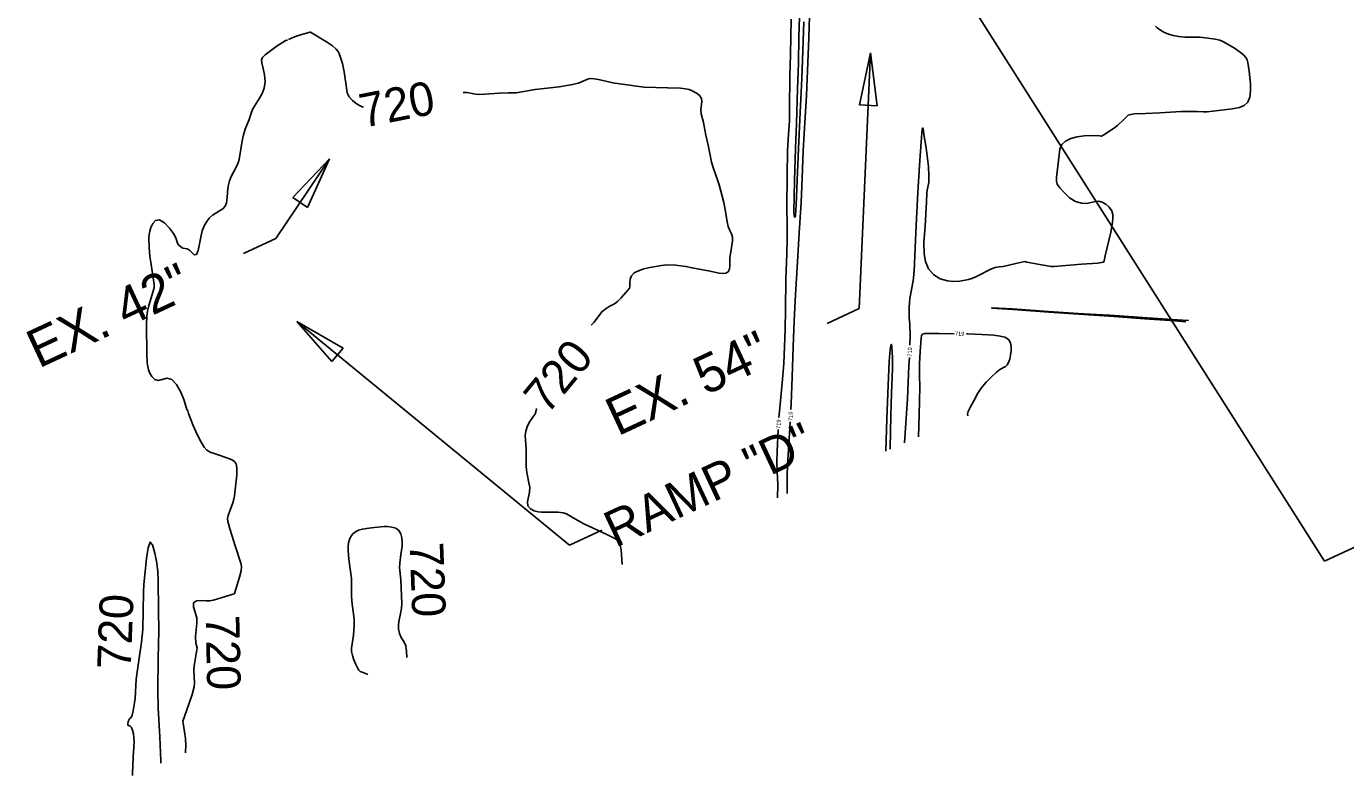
# Model space of a CAD drawing. Extents: x -310467766 to 17062430, y -322263100 to 8322522.
# Drawn here: x 1396172 to 1397464, y 572172 to 572906 of the extents above; entities that cross this region are included whole.
import ezdxf

# ---------------------------------------------------------------- set-up
doc = ezdxf.new("R2010")
doc.units = 0
for name, color, linetype in [('DT_X_Contour_Minor', 7, 'Continuous'), ('Level 19', 7, 'Continuous'), ('Level 40', 7, 'Continuous')]:
    doc.layers.add(name, color=color, linetype=linetype)

msp = doc.modelspace()

# ---------------------------------------------------------------- linework, layer by layer
at = {"layer": 'DT_X_Contour_Minor'}
for points in [[(1396939.3, 572926.2), (1396938.5, 572894.7), (1396937.1, 572862.4), (1396936, 572838), (1396934.1, 572806.2), (1396932.9, 572783.7), (1396931.9, 572757.4), (1396930.7, 572733.3), (1396928.9, 572703.5), (1396927.2, 572675.2), (1396925.2, 572642.8), (1396924, 572617.6), (1396923.1, 572591.8), (1396922.1, 572562), (1396921, 572536), (1396920.7, 572530.3)], [(1396929.6, 572924.9), (1396928.7, 572895.1), (1396928.1, 572869.8), (1396927.4, 572844.7), (1396926.2, 572810.5), (1396925.4, 572786.2), (1396924.4, 572754.4), (1396923.8, 572724.4), (1396924, 572720.5), (1396924.4, 572719), (1396924.7, 572718.8), (1396925, 572719), (1396925.3, 572720.4), (1396926, 572730.9), (1396927.4, 572763.1), (1396928.6, 572793.3), (1396929.8, 572821.4), (1396931.4, 572854.9), (1396932.5, 572881.7), (1396933.5, 572910.4)], [(1396909.1, 572522.6), (1396909.8, 572531.7), (1396912.8, 572563.6), (1396913.7, 572575.5), (1396915.1, 572608.8), (1396915.5, 572628.2), (1396915.9, 572658.2), (1396916.8, 572682.9), (1396917.2, 572697.2), (1396917, 572710.3), (1396916.8, 572729.3), (1396917.2, 572758.9), (1396917.3, 572784.6), (1396918.4, 572800), (1396919.3, 572813.3), (1396919.5, 572825.4), (1396919.7, 572857), (1396920.3, 572878.2), (1396920.9, 572912.9)], [(1396501.9, 572826.8), (1396500, 572827.2), (1396497.9, 572828.3), (1396494.7, 572830.4), (1396491.1, 572833.2), (1396488, 572836.7), (1396486.1, 572840.8), (1396485.2, 572845.5), (1396483.1, 572861.3), (1396481.3, 572869.6), (1396478.1, 572879.2), (1396477.1, 572881.1), (1396475.1, 572883.6), (1396471.5, 572886.8), (1396465.8, 572890.6), (1396450, 572900.1), (1396449.6, 572900.1), (1396440.1, 572897.5), (1396434.2, 572895.5)], [(1397368.5, 572831.5), (1397370.6, 572836.6), (1397371.2, 572842.8), (1397371, 572849.6), (1397369.8, 572861.9), (1397368.6, 572870.3), (1397367.9, 572872.9), (1397366.6, 572875.3), (1397364.3, 572877.8), (1397361.5, 572880.2), (1397355.5, 572884.4), (1397344.6, 572890.8), (1397341, 572892.2), (1397336.4, 572893.3), (1397327.1, 572894.6), (1397321.1, 572895.1), (1397306.9, 572895.3), (1397300.9, 572895.8), (1397295.5, 572896.9), (1397290.7, 572898.3), (1397286.8, 572899.9), (1397283.9, 572901.5), (1397279.7, 572904.5), (1397278, 572906.1)], [(1396427.5, 572892.6), (1396425.2, 572891.5), (1396417.5, 572886.9), (1396410.7, 572882), (1396405.7, 572877.9), (1396402.9, 572875.3), (1396402, 572873.1), (1396402.5, 572870), (1396403.8, 572864.7), (1396405.1, 572858.2), (1396405.5, 572851.4), (1396404.6, 572845.4), (1396402.6, 572840.1), (1396400.1, 572835.6), (1396393.5, 572825.1), (1396392.2, 572821.9), (1396389.9, 572814.7), (1396386.1, 572805.1), (1396384.4, 572799.6), (1396383.1, 572793.8), (1396380.1, 572775.4), (1396379.3, 572772.1), (1396377.6, 572768.5), (1396374.6, 572763.1), (1396372.6, 572759.2), (1396370.7, 572754.5), (1396369.4, 572749.2), (1396368.8, 572743.4), (1396368.5, 572737.8), (1396367.8, 572733), (1396366.3, 572729.5), (1396364, 572727), (1396361, 572725), (1396354.1, 572720.7), (1396350.9, 572718), (1396348.3, 572714.6), (1396346.2, 572711.1), (1396343.8, 572705.3), (1396343.1, 572702.5), (1396340, 572686.1), (1396338.3, 572682.1), (1396336.2, 572681.8), (1396331.5, 572686.5), (1396329.3, 572687.8), (1396325, 572688.6), (1396322.9, 572689.7), (1396321, 572691.5), (1396319.7, 572693.5), (1396318, 572698.6), (1396315.9, 572702.7), (1396311.9, 572708.1), (1396306.9, 572713.3), (1396302, 572716.3), (1396298.2, 572715.7), (1396295.5, 572712.6), (1396293.7, 572708.6), (1396292.6, 572705.2), (1396291.9, 572702), (1396291.7, 572698.3), (1396292, 572688.9), (1396292.6, 572680.6), (1396293.9, 572672.6), (1396297, 572652.7), (1396296.9, 572649.8), (1396296, 572646.4), (1396291.7, 572632.4), (1396290.3, 572626.7), (1396289.6, 572621.9), (1396289.3, 572613.7), (1396289.7, 572584.5), (1396290.1, 572576), (1396290.5, 572572.4), (1396291.3, 572569.2), (1396292.6, 572565.9), (1396294.7, 572562.6), (1396297.5, 572559.9), (1396300.9, 572558.9), (1396309.5, 572561.1), (1396314.2, 572559.9), (1396318.8, 572554.7), (1396322.9, 572547.3), (1396325.9, 572540.1), (1396328.3, 572532.6), (1396329, 572530.3), (1396329.9, 572529.2), (1396330.5, 572526.5), (1396332.1, 572522.1), (1396335.2, 572514.7), (1396339, 572506), (1396342.8, 572498.3), (1396345.8, 572493.3), (1396348.6, 572490.5), (1396351.8, 572488.7), (1396360.5, 572485.5), (1396371.8, 572481.8), (1396374.2, 572480.4), (1396376.1, 572478.7), (1396377.4, 572476.1), (1396378, 572472), (1396377.7, 572466.2), (1396375.5, 572445.6)], [(1396428.5, 572893), (1396434.2, 572895.5)], [(1396725.1, 572612.9), (1396728, 572616.1), (1396735.4, 572626.2), (1396739.9, 572629.5), (1396742.7, 572631.2), (1396748, 572634), (1396751, 572636.3), (1396754.6, 572639.9), (1396761, 572647.3), (1396762.6, 572649.3), (1396763.1, 572650.5), (1396763, 572654.8), (1396763.3, 572658.2), (1396764.6, 572661.5), (1396767.3, 572664.2), (1396771.3, 572666.3), (1396776.6, 572668.1), (1396782.7, 572669.5), (1396793.9, 572671.5), (1396799.8, 572672.2), (1396807.6, 572671.7), (1396817.9, 572670.5), (1396824, 572669.1), (1396831, 572667.8), (1396840.1, 572666.3), (1396850.5, 572664), (1396853.9, 572663.7), (1396857.1, 572664.1), (1396859.4, 572665.4), (1396860.6, 572667.9), (1396861, 572671.2), (1396861.1, 572678.9), (1396861.5, 572682.9), (1396863.6, 572695.3), (1396863.6, 572699.1), (1396862.5, 572702.5), (1396860.8, 572705.8), (1396859.2, 572709.6), (1396858.2, 572714.2), (1396856.4, 572726.2), (1396855, 572733.3), (1396850.6, 572750.4), (1396848.7, 572755.4), (1396844.8, 572766.6), (1396843, 572772.6), (1396841.2, 572781.1), (1396839.6, 572789.5), (1396837.5, 572799.1), (1396835.3, 572811.5), (1396833, 572820.2), (1396832.5, 572824.4), (1396833.4, 572831.9), (1396833.1, 572835), (1396831.4, 572837.7), (1396828.8, 572840), (1396823.5, 572843.1), (1396821, 572844), (1396817.5, 572844.7), (1396812.6, 572845.2), (1396799.9, 572845.7), (1396776.6, 572846.1), (1396751, 572849.7), (1396747.9, 572850.2), (1396733.7, 572853.5), (1396728.3, 572854.5), (1396724.7, 572854.8), (1396722.4, 572854.4), (1396715.7, 572851.4), (1396712.5, 572850.3), (1396705, 572848.5), (1396693.8, 572846.6), (1396670.3, 572843.9), (1396651.6, 572840.8), (1396643.7, 572840.6), (1396635.3, 572840.4), (1396616.1, 572839.2), (1396611.8, 572839.4), (1396603.7, 572841), (1396599.6, 572841.1)], [(1397037.4, 572593.3), (1397037.5, 572602.7), (1397037.2, 572613.7), (1397036.7, 572620.5), (1397036.8, 572630.7), (1397037.2, 572639.3), (1397040.5, 572656.5), (1397041.5, 572665.9), (1397042.4, 572688.8), (1397043.4, 572711), (1397045.3, 572742.9), (1397047.2, 572774.6), (1397049, 572801.3), (1397049.4, 572804.6), (1397049.9, 572806.3), (1397050.4, 572805.4), (1397051.4, 572797.9), (1397052.1, 572794.4), (1397053.4, 572786.7), (1397055.5, 572768.4), (1397056, 572759.3), (1397055.8, 572752.7), (1397054.4, 572745.2), (1397053.9, 572742.5), (1397053.5, 572733.9), (1397052.3, 572709.8), (1397051.1, 572694.1), (1397051.5, 572683), (1397052.7, 572675.3), (1397055.6, 572668.1), (1397060.7, 572662.4), (1397067.2, 572658.5), (1397074.1, 572656.3), (1397080.6, 572655.7), (1397086.2, 572656.2), (1397094.7, 572657.8), (1397098.1, 572658.8), (1397102.1, 572660.4), (1397117.5, 572668.2), (1397121, 572669.5), (1397124.9, 572670.1), (1397128.7, 572670.6), (1397141.3, 572673.4), (1397150, 572675.3), (1397152.1, 572674.9), (1397166.4, 572672), (1397175.7, 572670.6), (1397178.7, 572670.5), (1397205.7, 572672.9), (1397221.7, 572673.8), (1397226.7, 572674.7), (1397227.4, 572675.2), (1397227.7, 572676.1), (1397228.7, 572680.9), (1397234.2, 572704.3), (1397235.8, 572713.6), (1397236.4, 572717.6), (1397236.3, 572721.3), (1397235.2, 572725), (1397232.7, 572728.6), (1397229.3, 572731.7), (1397225.7, 572733.7), (1397222.4, 572734.4), (1397219.1, 572734.1), (1397210.8, 572732.4), (1397205.4, 572732.5), (1397199.7, 572734.1), (1397193.8, 572737.9), (1397188.4, 572742.9), (1397184.2, 572747.6), (1397181.8, 572751.1), (1397180.9, 572754.1), (1397181, 572757.7), (1397184.4, 572785.5), (1397186.3, 572789.9), (1397189.9, 572793.4), (1397195, 572796), (1397201.2, 572797.6), (1397208.2, 572798.5), (1397214.9, 572798.8), (1397223.1, 572798.4), (1397225.3, 572798.3), (1397227.4, 572799.6), (1397236.8, 572805.7), (1397240.7, 572808.7), (1397247, 572814.7), (1397249.4, 572817), (1397251.4, 572818.7), (1397253.8, 572819.6), (1397257.2, 572820.1), (1397268.4, 572820.6), (1397282.4, 572821.1), (1397303.3, 572822.4), (1397319.1, 572822.3), (1397325.1, 572822.1), (1397328.7, 572822.2), (1397345.5, 572824), (1397353.3, 572825), (1397360.3, 572826.4), (1397364.8, 572828.3), (1397368.5, 572831.5)], [(1397310.3, 572617.5), (1397299.6, 572618.2), (1397270.1, 572620.2), (1397233.3, 572622.8), (1397231.9, 572622.8), (1397202.3, 572624.6), (1397173.3, 572626.5), (1397137.8, 572629), (1397124.4, 572629.8), (1397117.4, 572629.8), (1397138.1, 572628.3), (1397173.5, 572625.7), (1397202.9, 572623.8), (1397237.4, 572621.6), (1397267.4, 572619.3), (1397297.1, 572617.2), (1397307.8, 572616.4)], [(1397080.8, 572604.6), (1397065.7, 572604.7), (1397051.9, 572604.7), (1397049.9, 572604.2), (1397048.8, 572602.8), (1397048.3, 572600.4), (1397047.4, 572587.2), (1397046.8, 572575.2), (1397046.9, 572563.6), (1397047.1, 572552.6), (1397046.4, 572525.2), (1397045.9, 572503.5)], [(1397094, 572524.2), (1397093.9, 572525.8), (1397094.4, 572528.4), (1397096.8, 572532.9), (1397099.9, 572538.7), (1397103.8, 572546.4), (1397107.2, 572551.4), (1397112, 572557), (1397117.5, 572562.5), (1397122.3, 572566.9), (1397125.6, 572569.4), (1397131, 572572.4), (1397132.6, 572574), (1397134, 572576.4), (1397135.2, 572579.7), (1397136, 572583.5), (1397136.5, 572587.7), (1397136.5, 572591.8), (1397135.9, 572595.4), (1397134.6, 572598.3), (1397132.6, 572600.1), (1397130.3, 572601.1), (1397125.8, 572602.2), (1397119.6, 572603.1), (1397107.9, 572604), (1397094.1, 572604.5), (1397092.8, 572604.5)], [(1397018.1, 572491.5), (1397018.1, 572492.9), (1397018.8, 572524.1), (1397019.5, 572546.5), (1397020.4, 572570.6), (1397020.3, 572581.3), (1397019.8, 572591.7), (1397019.3, 572594.2), (1397018.7, 572593.1), (1397018.1, 572589.2), (1397017.1, 572577.4), (1397016.1, 572554.2), (1397014.9, 572521.3), (1397013.7, 572489.6)], [(1397032.2, 572497.6), (1397034, 572526.4), (1397035, 572540.9), (1397036.5, 572573), (1397037, 572581.4)], [(1396755.6, 572378.3), (1396754.4, 572392.9), (1396753.5, 572397.3), (1396752.4, 572400.3), (1396750.8, 572402.3), (1396748.2, 572403.9), (1396740.4, 572407.9), (1396718, 572418.3), (1396707.5, 572424.1), (1396701, 572428.1), (1396697.5, 572429.2), (1396692.7, 572429.8), (1396682.6, 572429.9), (1396676.3, 572429.7), (1396673.2, 572430.1), (1396669.3, 572431.1), (1396665.5, 572433), (1396663, 572435.9), (1396662.7, 572439.9), (1396664.7, 572449.5), (1396664.8, 572454.1), (1396664.1, 572458.5), (1396662.2, 572466.9), (1396661.6, 572471), (1396661.3, 572475.1), (1396661.3, 572491.8), (1396660.6, 572500.3), (1396660.5, 572504.8), (1396661, 572509.2), (1396662.3, 572513.5), (1396664.2, 572517.5), (1396668.7, 572523.7), (1396670.1, 572525.8), (1396671, 572528), (1396671.6, 572531.3)], [(1396907.8, 572443.9), (1396907.9, 572456.8), (1396907.4, 572469.3), (1396907, 572479.2), (1396907.2, 572489.5), (1396908.2, 572510.5), (1396908.3, 572510.6)], [(1396920.1, 572518.4), (1396919.8, 572512.3), (1396917.6, 572475.4), (1396917.1, 572465.7), (1396917, 572447.9)], [(1396375.5, 572445.6), (1396375, 572442.6), (1396373.9, 572438.9), (1396369.2, 572426.5), (1396368.7, 572423.4), (1396369, 572420.5), (1396371.3, 572412.3), (1396376.1, 572396.9), (1396381.9, 572379.8), (1396382.4, 572376.4), (1396382, 572372.1), (1396380.6, 572366.2), (1396375.6, 572350.1), (1396375.3, 572349.8), (1396372, 572348.7), (1396358.3, 572344.5), (1396354.7, 572343.5), (1396351.5, 572343), (1396347.8, 572342.9), (1396343, 572343.1), (1396338.3, 572342.8), (1396335.4, 572341), (1396335.3, 572337), (1396338.5, 572326.1), (1396338.8, 572321), (1396337.5, 572308), (1396337.6, 572301.3)], [(1396538.6, 572363.5), (1396537.3, 572375.5), (1396537.5, 572379.7), (1396538.7, 572388.4), (1396539.7, 572396.4), (1396539.9, 572400.4), (1396539.6, 572404.6), (1396538.6, 572408.6), (1396536.7, 572411.8), (1396533.5, 572414), (1396529.6, 572415.1), (1396525.6, 572415.6), (1396521.8, 572415.6), (1396509.7, 572414.4), (1396505.2, 572413.9), (1396500.9, 572413.1), (1396497.2, 572412), (1396494.1, 572410.5), (1396491.6, 572408.5), (1396489.6, 572405.9), (1396488.2, 572403), (1396487.3, 572399.6), (1396486.9, 572396), (1396486.8, 572392.1), (1396487.5, 572383.8), (1396490.3, 572364.6), (1396490.3, 572355.5), (1396490.3, 572347.2), (1396491, 572339.6), (1396492.2, 572330.1), (1396492.7, 572324.7), (1396492.8, 572319.1), (1396492.6, 572313.8), (1396492.2, 572309.2), (1396490.1, 572296.5), (1396490.3, 572293.1), (1396491.1, 572289.2), (1396492.5, 572284.9), (1396494.3, 572280.6), (1396496, 572277.1), (1396497.5, 572274.9), (1396498.8, 572273.7), (1396500.8, 572272.9), (1396505.5, 572271.1), (1396506.2, 572270.8)], [(1396303.5, 572183.6), (1396303.4, 572186), (1396302.4, 572209.6), (1396300.8, 572237.6), (1396300.4, 572255.3), (1396300.7, 572286.5), (1396301.3, 572313.5), (1396301.1, 572333.3), (1396300.6, 572363.4), (1396300.3, 572371.2), (1396299.4, 572379.8), (1396297.6, 572389.7), (1396295.3, 572397.8), (1396292.9, 572400.4), (1396290.8, 572394.8), (1396289.2, 572384.3), (1396286.7, 572358.7), (1396286.3, 572351.2), (1396285.8, 572314.8)], [(1396544.5, 572287.3), (1396544.2, 572293.4), (1396543.4, 572298.6), (1396541.4, 572303), (1396539, 572306.9), (1396537.1, 572310.9), (1396536.2, 572315.3), (1396536.3, 572319.8), (1396537, 572324.2), (1396538.7, 572331.8), (1396539.3, 572335.8), (1396539.5, 572340.2), (1396538.6, 572363.5)], [(1396285.8, 572314.8), (1396284.3, 572302.3), (1396281.1, 572279.9), (1396279.3, 572266.2), (1396278.2, 572247.2), (1396277.4, 572240.9), (1396276.4, 572235.2), (1396275.2, 572230.9), (1396274.2, 572228.5), (1396272.7, 572227.1), (1396272.2, 572226.6), (1396271.4, 572224.6), (1396270.9, 572222), (1396271.2, 572221.1), (1396273.3, 572220), (1396274.6, 572218.6), (1396275.7, 572216.1), (1396276.5, 572212.6), (1396277, 572208.7), (1396277.1, 572204.8), (1396276.3, 572189.5), (1396275.6, 572173.5), (1396275.6, 572171.6)], [(1396337.6, 572301.3), (1396339.1, 572296.8), (1396335.9, 572279), (1396335.6, 572274.9), (1396336.5, 572262.6), (1396336, 572258.5), (1396334.1, 572251), (1396330.8, 572241.7), (1396324.9, 572225), (1396325.1, 572222.8), (1396326.7, 572214.5), (1396327.6, 572207.9), (1396328, 572201.1), (1396327.6, 572194.7), (1396327.4, 572193.9)]]:
    msp.add_lwpolyline(points, dxfattribs=at)
at = {"layer": 'Level 40'}
for p, q in [((1397041, 573015.9), (1397443.7, 572381.8)), ((1396998.9, 572880), (1396987.8, 572629.4)), ((1396988, 572828.8), (1396998.9, 572880)), ((1396998.9, 572880), (1397005.2, 572828)), ((1397005.2, 572828), (1396988, 572828.8)), ((1396468.8, 572776), (1396416.1, 572697.9)), ((1396432.8, 572738), (1396468.8, 572776)), ((1396468.8, 572776), (1396447, 572728.4)), ((1397443.7, 572381.8), (1398254.3, 572759.8)), ((1396447, 572728.4), (1396432.8, 572738)), ((1396384.3, 572683.1), (1396416.1, 572697.9)), ((1396956.2, 572614.7), (1396987.8, 572629.4)), ((1396703.9, 572397.4), (1396436.7, 572616.6)), ((1396471.1, 572577.3), (1396436.7, 572616.6)), ((1396436.7, 572616.6), (1396482, 572590.6)), ((1396482, 572590.6), (1396471.1, 572577.3)), ((1396703.9, 572397.4), (1396735.5, 572412.1))]:
    msp.add_line(p, q, dxfattribs=at)

# ---------------------------------------------------------------- texts
at = {"layer": 'Level 19'}
for s, height, rotation, p in [('720', 33, 11.0581, (1396501.6, 572806.4)), ('719', 4, 359.4279, (1397081.5, 572602.6)), ('720', 33, 50.4776, (1396682, 572524.4)), ('719', 4, 88.9689, (1397039.2, 572582.1)), ('719', 4, 87.0953, (1396922.2, 572519)), ('719', 4, 85.8463, (1396910.3, 572511.2)), ('720', 33, 272.1435, (1396547.1, 572399.8)), ('720', 33, 87.8459, (1396273.9, 572275.3)), ('720', 33, 271.1695, (1396347.3, 572328.6))]:
    msp.add_text(s, height=height, rotation=rotation, dxfattribs=at).set_placement(p)
at = {"layer": 'Level 40'}
for s, height, p in [('EX. 42"', 37.5, (1396183.7, 572570.3)), ('EX. 54"', 37.5, (1396751.1, 572503.9)), ('RAMP "D"', 35.5, (1396748.8, 572394.6))]:
    msp.add_text(s, height=height, rotation=25, dxfattribs=at).set_placement(p)

doc.saveas('drawing.dxf')
